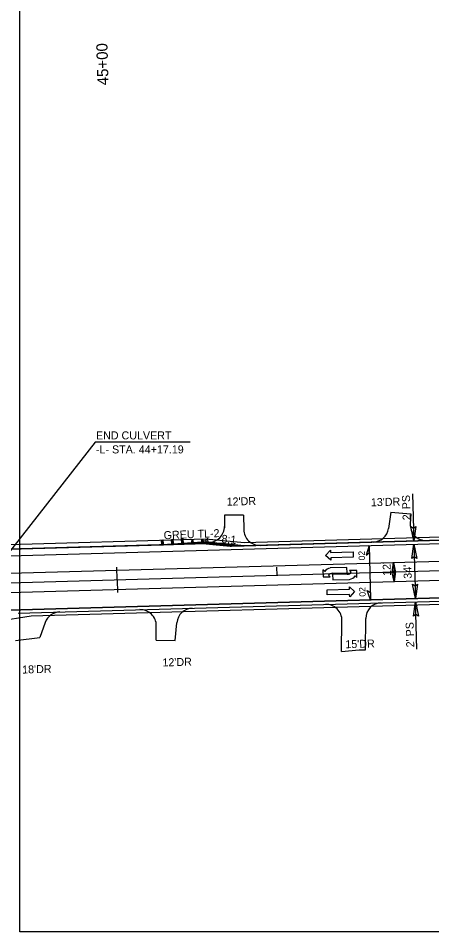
# Model space of a CAD drawing. Extents: x 1755545 to 1761252, y 736169 to 737766.
# Drawn here: x 1759121 to 1759380, y 736805 to 737376 of the extents above; entities that cross this region are included whole.
import ezdxf

# ---------------------------------------------------------------- set-up
doc = ezdxf.new("R2010")
doc.units = 0
for name, color, linetype in [('Exist Contamination Potential Cell', 7, 'Continuous'), ('Exist Cultural Church Label', 7, 'Continuous'), ('Old_Level_1', 7, 'Continuous'), ('Prop Dimension', 7, 'Continuous'), ('Prop Guardrail', 7, 'Continuous'), ('Prop Guardrail Anchor Unit CELL', 7, 'Continuous'), ('Prop Horizontal Alignment', 7, 'Continuous'), ('Prop Horizontal Alignment Tick Label', 7, 'Continuous'), ('Prop Horizontal Alignment Tick Large', 7, 'Continuous'), ('Prop Horizontal Alignment Tick Small', 7, 'Continuous'), ('Prop Lane Arrow CELL', 7, 'Continuous'), ('Prop Lane Lines', 7, 'Continuous'), ('Prop Paved Shoulder', 7, 'Continuous'), ('Prop Shade Light', 7, 'Continuous'), ('Prop Superelevation Label', 7, 'Continuous'), ('Prop Terminator CELL', 7, 'Continuous'), ('Scratch_Level_4', 7, 'Continuous'), ('Scratch_Level_5', 7, 'Continuous'), ('Scratch_Level_6', 7, 'Continuous')]:
    doc.layers.add(name, color=color, linetype=linetype)

msp = doc.modelspace()

# ---------------------------------------------------------------- linework, layer by layer
at = {"layer": 'Exist Contamination Potential Cell'}
for p, q in [((1759014.29, 737037.34), (1760207.22, 737071.22)), ((1757498.66, 736960.29), (1760222.11, 737037.63))]:
    msp.add_line(p, q, dxfattribs=at)
at = {"layer": 'Exist Cultural Church Label'}
for points in [[(1759340.57, 737046.61), (1759338.74, 737040.55), (1759340.7, 737041.99)], [(1759341.53, 737012.62), (1759339.36, 737018.56), (1759341.4, 737017.25)]]:
    msp.add_lwpolyline(points, close=True, dxfattribs=at)
at = {"layer": 'Old_Level_1'}
for p, q in [((1759250.32, 737065.42), (1759250.28, 737057.56)), ((1759262.17, 737065.59), (1759250.32, 737065.42)), ((1759262.17, 737065.59), (1759262.27, 737056.56)), ((1759354.26, 737067.31), (1759352.75, 737057.2)), ((1759354.26, 737067.31), (1759366.67, 737066.42)), ((1759366.67, 737066.42), (1759366.33, 737060.18)), ((1759138.31, 736998.47), (1759134.95, 736989.05)), ((1759219.45, 736987.16), (1759220.49, 736998.38)), ((1759323.39, 736980.39), (1759323.67, 736999.68)), ((1759338.31, 736981.49), (1759338.48, 737000.9)), ((1759207.62, 736987.48), (1759207.67, 736996.48)), ((1759119.75, 736987.31), (1759134.95, 736989.05)), ((1759207.62, 736987.48), (1759219.45, 736987.16)), ((1759323.39, 736980.39), (1759334.43, 736981.39)), ((1759334.43, 736981.39), (1759338.31, 736981.49))]:
    msp.add_line(p, q, dxfattribs=at)
for centre, start, end in [((1759376.31, 737059.63), 176.8318, 271.6265), ((1759240.29, 737058.57), 268.7828, 359.7406), ((1759272.27, 737056.67), 180.6572, 271.6265), ((1759342.86, 737058.68), 271.6265, 351.4873), ((1759313.67, 736999.83), 359.1469, 91.6265), ((1759348.48, 737000.81), 91.6265, 179.506), ((1759147.73, 736995.11), 91.6265, 160.3788), ((1759197.67, 736996.53), 359.7155, 91.6265), ((1759230.44, 736997.46), 91.6265, 174.7336)]:
    msp.add_arc(centre, 10, start, end, dxfattribs=at)
at = {"layer": 'Prop Dimension'}
for p, q in [((1759169.57, 737111.19), (1759100.35, 737022.78)), ((1759228.77, 737111.19), (1759169.57, 737111.19)), ((1759367.73, 737078.87), (1759368.56, 737049.4)), ((1759368.62, 737047.4), (1759369.58, 737013.42)), ((1759355.87, 737036.04), (1759356.21, 737024.04)), ((1759370.48, 736981.95), (1759369.64, 737011.42))]:
    msp.add_line(p, q, dxfattribs=at)
at = {"layer": 'Prop Guardrail'}
msp.add_line((1759211.17, 737046.94), (1759062.23, 737042.71), dxfattribs=at)
at = {"layer": 'Prop Guardrail Anchor Unit CELL'}
for p, q in [((1759210.98, 737049.96), (1759211.98, 737050.03)), ((1759211.17, 737046.94), (1759210.98, 737049.96)), ((1759212.07, 737048.52), (1759210.98, 737049.96)), ((1759211.98, 737050.03), (1759211.08, 737048.45)), ((1759211.08, 737048.45), (1759212.07, 737048.52)), ((1759211.08, 737048.45), (1759212.17, 737047)), ((1759211.17, 737046.94), (1759212.07, 737048.52)), ((1759236.62, 737048.57), (1759211.67, 737046.97)), ((1759212.17, 737047), (1759211.98, 737050.03)), ((1759217.21, 737050.37), (1759218.21, 737050.43)), ((1759217.41, 737047.34), (1759217.21, 737050.37)), ((1759218.31, 737048.92), (1759217.21, 737050.37)), ((1759218.21, 737050.43), (1759217.31, 737048.85)), ((1759217.31, 737048.85), (1759218.31, 737048.92)), ((1759217.31, 737048.85), (1759218.41, 737047.4)), ((1759217.41, 737047.34), (1759218.31, 737048.92)), ((1759218.41, 737047.4), (1759218.21, 737050.43)), ((1759223.45, 737050.77), (1759224.45, 737050.83)), ((1759223.65, 737047.74), (1759223.45, 737050.77)), ((1759224.55, 737049.32), (1759223.45, 737050.77)), ((1759224.45, 737050.83), (1759223.55, 737049.25)), ((1759223.55, 737049.25), (1759224.55, 737049.32)), ((1759223.55, 737049.25), (1759224.65, 737047.8)), ((1759223.65, 737047.74), (1759224.55, 737049.32)), ((1759224.65, 737047.8), (1759224.45, 737050.83)), ((1759229.79, 737049.66), (1759230.78, 737049.72)), ((1759229.88, 737048.14), (1759229.79, 737049.66)), ((1759229.79, 737049.66), (1759230.88, 737048.2)), ((1759229.88, 737048.14), (1759230.78, 737049.72)), ((1759229.88, 737048.14), (1759230.88, 737048.2)), ((1759230.88, 737048.2), (1759230.78, 737049.72)), ((1759236.02, 737050.06), (1759237.02, 737050.12)), ((1759236.12, 737048.54), (1759236.02, 737050.06)), ((1759236.02, 737050.06), (1759237.12, 737048.61)), ((1759236.12, 737048.54), (1759237.02, 737050.12)), ((1759236.12, 737048.54), (1759237.12, 737048.61)), ((1759237.12, 737048.61), (1759237.02, 737050.12)), ((1759238.54, 737049.43), (1759237.07, 737049.33)), ((1759237.12, 737048.62), (1759238.59, 737048.71)), ((1759239.62, 737050.87), (1759238.51, 737049.94)), ((1759238.51, 737049.94), (1759238.59, 737048.71)), ((1759238.59, 737048.71), (1759239.82, 737047.93)), ((1759239.62, 737050.87), (1759239.93, 737050.89)), ((1759239.82, 737047.93), (1759240.12, 737047.95)), ((1759240.12, 737047.95), (1759239.93, 737050.89)), ((1759211.17, 737046.94), (1759212.17, 737047)), ((1759217.41, 737047.34), (1759218.41, 737047.4)), ((1759223.65, 737047.74), (1759224.65, 737047.8))]:
    msp.add_line(p, q, dxfattribs=at)
at = {"layer": 'Prop Horizontal Alignment'}
msp.add_line((1757285.64, 736971.25), (1760282.69, 737056.35), dxfattribs=at)
at = {"layer": 'Prop Horizontal Alignment Tick Large'}
for q in [(1759182.91, 737033.13), (1759183.36, 737017.13)]:
    msp.add_line((1759183.13, 737025.13), q, dxfattribs=at)
at = {"layer": 'Prop Horizontal Alignment Tick Small'}
msp.add_line((1759283.09, 737027.97), (1759282.95, 737032.97), dxfattribs=at)
at = {"layer": 'Prop Lane Arrow CELL'}
for p, q in [((1759313.47, 737040.39), (1759316.53, 737043.68)), ((1759316.53, 737043.68), (1759316.57, 737042.18)), ((1759316.57, 737042.18), (1759330.57, 737042.58)), ((1759330.57, 737042.58), (1759330.66, 737039.28)), ((1759316.71, 737037.38), (1759313.47, 737040.39)), ((1759330.66, 737039.28), (1759316.67, 737038.88)), ((1759316.67, 737038.88), (1759316.71, 737037.38)), ((1759312.87, 737030.35), (1759311.74, 737031.36)), ((1759311.74, 737031.36), (1759311.87, 737026.92)), ((1759326.8, 737032.84), (1759316.26, 737032.54)), ((1759326.9, 737029.54), (1759326.8, 737032.84)), ((1759332.86, 737030.96), (1759328.36, 737030.89)), ((1759328.36, 737030.89), (1759329.44, 737029.87)), ((1759332.94, 737026.56), (1759332.86, 737030.96)), ((1759311.87, 737026.92), (1759316.36, 737027.04)), ((1759316.36, 737027.04), (1759315.29, 737028.06)), ((1759317.75, 737029.28), (1759326.9, 737029.54)), ((1759326.97, 737028.65), (1759317.83, 737028.39)), ((1759317.83, 737028.39), (1759317.92, 737025.09)), ((1759317.92, 737025.09), (1759328.47, 737025.39)), ((1759331.86, 737027.58), (1759332.94, 737026.56)), ((1759328.35, 737019.36), (1759328.31, 737020.86)), ((1759328.31, 737020.86), (1759331.55, 737017.85)), ((1759314.36, 737018.97), (1759328.35, 737019.36)), ((1759314.45, 737015.67), (1759314.36, 737018.97)), ((1759328.45, 737016.06), (1759314.45, 737015.67)), ((1759328.49, 737014.56), (1759328.45, 737016.06)), ((1759331.55, 737017.85), (1759328.49, 737014.56))]:
    msp.add_line(p, q, dxfattribs=at)
for centre, radius, start, end in [((1759317.19, 737027.36), 5.25, 100.3026, 145.6143), ((1759317.82, 737026), 3.28, 91.6265, 141.2847), ((1759326.89, 737031.9), 3.28, 271.6265, 321.2847), ((1759327.53, 737030.54), 5.25, 280.3026, 325.6143)]:
    msp.add_arc(centre, radius, start, end, dxfattribs=at)
at = {"layer": 'Prop Lane Lines'}
for p, q in [((1757285.47, 736977.25), (1760207.53, 737060.22)), ((1757285.81, 736965.25), (1760207.87, 737048.23))]:
    msp.add_line(p, q, dxfattribs=at)
at = {"layer": 'Prop Paved Shoulder'}
for p, q in [((1759262.66, 737046.4), (1760207.16, 737073.22)), ((1759211.18, 737046.94), (1759238.59, 737048.71)), ((1759238.59, 737048.71), (1759262.66, 737046.4)), ((1759062.23, 737042.71), (1759211.18, 737046.94)), ((1759121.42, 737004.37), (1760222.17, 737035.63))]:
    msp.add_line(p, q, dxfattribs=at)
msp.add_spline([(1759238.59, 737048.71), (1759238.8, 737048.69), (1759239.02, 737048.67), (1759239.24, 737048.65), (1759239.45, 737048.63), (1759239.67, 737048.61), (1759239.89, 737048.59), (1759240.1, 737048.57), (1759240.32, 737048.55), (1759240.54, 737048.53), (1759240.76, 737048.51), (1759240.97, 737048.48), (1759241.19, 737048.46), (1759241.41, 737048.44), (1759241.62, 737048.42), (1759241.84, 737048.4), (1759242.06, 737048.38), (1759242.27, 737048.36), (1759242.49, 737048.34), (1759242.71, 737048.32), (1759242.92, 737048.3), (1759243.14, 737048.28), (1759243.36, 737048.25), (1759243.58, 737048.23), (1759243.79, 737048.21), (1759244.01, 737048.19), (1759244.23, 737048.17), (1759244.44, 737048.15), (1759244.66, 737048.13), (1759244.88, 737048.11), (1759245.09, 737048.09), (1759245.31, 737048.07), (1759245.53, 737048.05), (1759245.74, 737048.02), (1759245.96, 737048), (1759246.18, 737047.98), (1759246.39, 737047.96), (1759246.61, 737047.94), (1759246.83, 737047.92), (1759247.05, 737047.9), (1759247.26, 737047.88), (1759247.48, 737047.86), (1759247.7, 737047.84), (1759247.91, 737047.82), (1759248.13, 737047.8), (1759248.35, 737047.77), (1759248.56, 737047.75), (1759248.78, 737047.73), (1759249, 737047.71), (1759249.21, 737047.69), (1759249.43, 737047.67), (1759249.65, 737047.65), (1759249.87, 737047.63), (1759250.08, 737047.61), (1759250.3, 737047.59), (1759250.52, 737047.57), (1759250.73, 737047.54), (1759250.95, 737047.52), (1759251.17, 737047.5), (1759251.38, 737047.48), (1759251.6, 737047.46), (1759251.82, 737047.44), (1759252.03, 737047.42), (1759252.25, 737047.4), (1759252.47, 737047.38), (1759252.68, 737047.36), (1759252.9, 737047.34), (1759253.12, 737047.31), (1759253.34, 737047.29), (1759253.55, 737047.27), (1759253.77, 737047.25), (1759253.99, 737047.23), (1759254.2, 737047.21), (1759254.64, 737047.17)], degree=3, dxfattribs=at)
at = {"layer": 'Prop Shade Light'}
for p, q in [((1759014.29, 737037.34), (1760207.22, 737071.22)), ((1760207.16, 737073.22), (1759254.68, 737046.17)), ((1759238.59, 737048.71), (1759211.18, 737046.94)), ((1759246.9, 737047.91), (1759244.31, 737048.16)), ((1759238.63, 737047.72), (1759034.78, 737041.93)), ((1759211.18, 737046.94), (1759238.63, 737047.72)), ((1759247.53, 737047.85), (1759247.47, 737047.86)), ((1759248.29, 737047.78), (1759248.02, 737047.81)), ((1759262.66, 737046.4), (1759254.64, 737047.17)), ((1759254.68, 737046.17), (1759262.66, 737046.4)), ((1760222.11, 737037.63), (1757498.66, 736960.29)), ((1759121.42, 737004.37), (1760222.17, 737035.63))]:
    msp.add_line(p, q, dxfattribs=at)
for points in [[(1759241.66, 737048.42), (1759241.54, 737048.43), (1759240.07, 737048.57)], [(1759244.13, 737048.18), (1759243.94, 737048.2), (1759243.47, 737048.24), (1759243.02, 737048.29), (1759242.88, 737048.3), (1759242.51, 737048.34), (1759242.43, 737048.34)]]:
    msp.add_lwpolyline(points, dxfattribs=at)
for points in [[(1759240.07, 737048.57), (1759239.89, 737048.59), (1759239.67, 737048.61), (1759239.45, 737048.63), (1759239.24, 737048.65), (1759239.02, 737048.67), (1759238.8, 737048.69), (1759238.59, 737048.71)], [(1759244.31, 737048.16), (1759244.23, 737048.17), (1759244.13, 737048.18)], [(1759243.98, 737047.2), (1759243.84, 737047.21), (1759243.62, 737047.24), (1759243.41, 737047.26), (1759243.19, 737047.28), (1759242.97, 737047.3), (1759242.76, 737047.32), (1759242.54, 737047.34), (1759242.32, 737047.36), (1759242.1, 737047.38), (1759241.89, 737047.4), (1759241.67, 737047.42), (1759241.45, 737047.44), (1759241.24, 737047.46), (1759241.02, 737047.49), (1759240.8, 737047.51), (1759240.59, 737047.53), (1759240.37, 737047.55), (1759240.15, 737047.57), (1759239.94, 737047.59), (1759239.72, 737047.61), (1759239.5, 737047.63), (1759239.28, 737047.65), (1759239.07, 737047.67), (1759238.85, 737047.69), (1759238.63, 737047.72)], [(1759238.63, 737047.72), (1759238.85, 737047.69), (1759239.07, 737047.67), (1759239.28, 737047.65), (1759239.5, 737047.63), (1759239.72, 737047.61), (1759239.94, 737047.59), (1759240.15, 737047.57), (1759240.37, 737047.55), (1759240.59, 737047.53), (1759240.8, 737047.51), (1759241.02, 737047.49), (1759241.24, 737047.46), (1759241.45, 737047.44), (1759241.67, 737047.42), (1759241.89, 737047.4), (1759242.1, 737047.38), (1759242.32, 737047.36), (1759242.54, 737047.34), (1759242.76, 737047.32), (1759242.97, 737047.3), (1759243.19, 737047.28), (1759243.41, 737047.26), (1759243.62, 737047.24), (1759243.84, 737047.21), (1759243.98, 737047.2)], [(1759249.33, 737046.69), (1759249.26, 737046.69), (1759249.05, 737046.71), (1759248.83, 737046.73), (1759248.61, 737046.76), (1759248.39, 737046.78), (1759248.18, 737046.8), (1759247.96, 737046.82), (1759247.74, 737046.84), (1759247.53, 737046.86), (1759247.31, 737046.88), (1759247.09, 737046.9), (1759246.88, 737046.92), (1759246.66, 737046.94), (1759246.44, 737046.96), (1759246.23, 737046.98), (1759246.01, 737047.01), (1759245.79, 737047.03), (1759245.57, 737047.05), (1759245.36, 737047.07), (1759245.14, 737047.09), (1759244.92, 737047.11), (1759244.71, 737047.13), (1759244.49, 737047.15), (1759244.27, 737047.17), (1759244.06, 737047.19), (1759243.98, 737047.2)], [(1759243.98, 737047.2), (1759244.06, 737047.19), (1759244.27, 737047.17), (1759244.49, 737047.15), (1759244.71, 737047.13), (1759244.92, 737047.11), (1759245.14, 737047.09), (1759245.36, 737047.07), (1759245.57, 737047.05), (1759245.79, 737047.03), (1759246.01, 737047.01), (1759246.23, 737046.98), (1759246.44, 737046.96), (1759246.66, 737046.94), (1759246.88, 737046.92), (1759247.09, 737046.9), (1759247.31, 737046.88), (1759247.53, 737046.86), (1759247.74, 737046.84), (1759247.96, 737046.82), (1759248.18, 737046.8), (1759248.39, 737046.78), (1759248.61, 737046.76), (1759248.83, 737046.73), (1759249.05, 737046.71), (1759249.26, 737046.69), (1759249.33, 737046.69)], [(1759254.64, 737047.17), (1759254.2, 737047.21), (1759253.99, 737047.23), (1759253.77, 737047.25), (1759253.55, 737047.27), (1759253.34, 737047.29), (1759253.12, 737047.31), (1759252.9, 737047.34), (1759252.68, 737047.36), (1759252.47, 737047.38), (1759252.25, 737047.4), (1759252.03, 737047.42), (1759251.82, 737047.44), (1759251.6, 737047.46), (1759251.38, 737047.48), (1759251.17, 737047.5), (1759250.95, 737047.52), (1759250.73, 737047.54), (1759250.52, 737047.57), (1759250.3, 737047.59), (1759250.08, 737047.61), (1759249.87, 737047.63), (1759249.65, 737047.65), (1759249.43, 737047.67), (1759249.29, 737047.68)], [(1759254.68, 737046.17), (1759254.25, 737046.21), (1759254.03, 737046.23), (1759253.82, 737046.25), (1759253.6, 737046.27), (1759253.38, 737046.3), (1759253.17, 737046.32), (1759252.95, 737046.34), (1759252.73, 737046.36), (1759252.52, 737046.38), (1759252.3, 737046.4), (1759252.08, 737046.42), (1759251.86, 737046.44), (1759251.65, 737046.46), (1759251.43, 737046.48), (1759251.21, 737046.5), (1759251, 737046.53), (1759250.78, 737046.55), (1759250.56, 737046.57), (1759250.35, 737046.59), (1759250.13, 737046.61), (1759249.91, 737046.63), (1759249.7, 737046.65), (1759249.48, 737046.67), (1759249.33, 737046.69)], [(1759249.33, 737046.69), (1759249.48, 737046.67), (1759249.7, 737046.65), (1759249.91, 737046.63), (1759250.13, 737046.61), (1759250.35, 737046.59), (1759250.56, 737046.57), (1759250.78, 737046.55), (1759251, 737046.53), (1759251.21, 737046.5), (1759251.43, 737046.48), (1759251.65, 737046.46), (1759251.86, 737046.44), (1759252.08, 737046.42), (1759252.3, 737046.4), (1759252.52, 737046.38), (1759252.73, 737046.36), (1759252.95, 737046.34), (1759253.17, 737046.32), (1759253.38, 737046.3), (1759253.6, 737046.27), (1759253.82, 737046.25), (1759254.03, 737046.23), (1759254.25, 737046.21), (1759254.68, 737046.17)]]:
    msp.add_spline(points, degree=3, dxfattribs=at)
for points in [[(1759242.43, 737048.34), (1759242.38, 737048.35), (1759242.33, 737048.35), (1759242.27, 737048.36), (1759242.2, 737048.37), (1759242.13, 737048.37), (1759242.06, 737048.38), (1759241.98, 737048.39), (1759241.91, 737048.39), (1759241.84, 737048.4), (1759241.78, 737048.41), (1759241.72, 737048.41), (1759241.66, 737048.42)], [(1759247.47, 737047.86), (1759247.4, 737047.87), (1759247.33, 737047.87), (1759247.26, 737047.88), (1759247.19, 737047.89), (1759247.12, 737047.89), (1759247.05, 737047.9), (1759247, 737047.9), (1759246.95, 737047.91), (1759246.9, 737047.91)], [(1759248.02, 737047.81), (1759247.98, 737047.81), (1759247.95, 737047.81), (1759247.91, 737047.82), (1759247.84, 737047.82), (1759247.77, 737047.83), (1759247.7, 737047.84), (1759247.64, 737047.84), (1759247.59, 737047.85), (1759247.53, 737047.85)], [(1759249.29, 737047.68), (1759249.26, 737047.69), (1759249.24, 737047.69), (1759249.21, 737047.69), (1759249.14, 737047.7), (1759249.07, 737047.7), (1759249, 737047.71), (1759248.93, 737047.72), (1759248.85, 737047.73), (1759248.78, 737047.73), (1759248.71, 737047.74), (1759248.64, 737047.75), (1759248.56, 737047.75), (1759248.49, 737047.76), (1759248.42, 737047.77), (1759248.35, 737047.77), (1759248.33, 737047.78), (1759248.31, 737047.78), (1759248.29, 737047.78)]]:
    msp.add_open_spline(points, degree=3, dxfattribs=at)
at = {"layer": 'Prop Superelevation Label'}
msp.add_line((1759340.57, 737046.61), (1759341.53, 737012.62), dxfattribs=at)
at = {"layer": 'Prop Terminator CELL'}
for points in [[(1759369.86, 737058.44), (1759368.56, 737049.4), (1759366.71, 737058.41), (1759368.34, 737057.3)], [(1759367.33, 737038.36), (1759368.62, 737047.4), (1759370.48, 737038.4), (1759368.84, 737039.51)], [(1759354.97, 737029.71), (1759355.87, 737036.04), (1759357.17, 737029.74), (1759356.03, 737030.51)], [(1759357.12, 737030.37), (1759356.21, 737024.04), (1759354.91, 737030.34), (1759356.06, 737029.57)], [(1759370.88, 737022.46), (1759369.58, 737013.42), (1759367.73, 737022.42), (1759369.36, 737021.32)], [(1759368.35, 737002.38), (1759369.64, 737011.42), (1759371.5, 737002.42), (1759369.87, 737003.52)]]:
    msp.add_lwpolyline(points, close=True, dxfattribs=at)
at = {"layer": 'Scratch_Level_5'}
for p, q in [((1759061.73, 737042.69), (1759211.67, 737046.95)), ((1759211.67, 737046.95), (1759238.63, 737047.73))]:
    msp.add_line(p, q, dxfattribs=at)
msp.add_lwpolyline([(1759122.38, 737765.89), (1760563.07, 737765.89), (1760563.07, 736805.42), (1759122.38, 736805.42)], close=True, dxfattribs=at)
at = {"layer": 'Scratch_Level_6'}
for p, q in [((1759262.62, 737048.4), (1760207.1, 737075.22)), ((1759033.21, 737044.88), (1759238.55, 737050.71)), ((1759238.55, 737050.71), (1759262.62, 737048.4)), ((1759129.47, 737002.6), (1760223.47, 737033.66)), ((1759105.57, 736998.92), (1759129.47, 737002.6))]:
    msp.add_line(p, q, dxfattribs=at)

# ---------------------------------------------------------------- texts
at = {"layer": 'Prop Dimension'}
for s, rotation, p in [('END CULVERT ', 360, (1759169.97, 737112.82)), ('-L- STA. 44+17.19 ', 360, (1759169.97, 737104.07)), ("2' PS", 91.6265, (1759366.58, 737062.41)), ('8:1', 354.5015, (1759248.2, 737048.38)), ("12'", 91.6265, (1759354.28, 737027.64)), ("34'", 91.6265, (1759367.26, 737025.88)), ("2' PS", 91.6265, (1759368.84, 736983.07))]:
    msp.add_text(s, height=5, rotation=rotation, dxfattribs=at).set_placement(p)
at = {"layer": 'Prop Guardrail Anchor Unit CELL'}
msp.add_text('GREU TL-2', height=5, rotation=2.2463, dxfattribs=at).set_placement((1759212.35, 737050.47))
at = {"layer": 'Prop Horizontal Alignment Tick Label'}
msp.add_text('45+00', height=7, rotation=91.6265, dxfattribs=at).set_placement((1759177.86, 737334.04))
at = {"layer": 'Prop Superelevation Label'}
for p in [(1759338.09, 737037.35), (1759338.47, 737014.68)]:
    msp.add_text('02', height=4, rotation=91.6265, dxfattribs=at).set_placement(p)
at = {"layer": 'Scratch_Level_4'}
for s, p in [("12'DR", (1759251.68, 737071.41)), ("13'DR", (1759341.8, 737071.04)), ("15'DR", (1759325.84, 736982.41)), ("12'DR", (1759211.57, 736971.04)), ("18'DR", (1759123.92, 736966.6))]:
    msp.add_text(s, height=5, rotation=1.6265, dxfattribs=at).set_placement(p)

doc.saveas('drawing.dxf')
